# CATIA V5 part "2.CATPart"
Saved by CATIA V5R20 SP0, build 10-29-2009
Part number: 2
Publications: "H", "K", "Droite.1", "Droite.2", "Droite.3", "Plan.1"
Bounding box of the stored display mesh (mm): x -14 to 10, y 8.275 to 71.642, z -121.494 to -78.745
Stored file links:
  D:\Dropbox\IAO_2012\IAO_2012_815_gcordenod\IAO_2012_815_gcordenod\2.CATPart
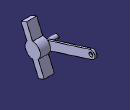
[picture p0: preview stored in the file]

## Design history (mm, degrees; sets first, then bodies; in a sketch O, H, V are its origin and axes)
Body1 (main body)
  Point1 "H": stored without definition
  Point2 "H": (0, 0, 0), relative to Point1
  Point3 "K": stored without definition
  Point4 "K": (0, 0, 0), relative to Point3
  Line1: type PtDir, RefPoint Point4, Direction yz-plane, Start -20, End 20
  Line2: type PtDir, RefPoint Point2, Direction yz-plane, Start -20, End 20
  Line3: type PtPt, FirstPoint Point2, SecondPoint Point4
  Plane1: type Offset, RefPlane yz-plane, Offset 0
  DatumCurve1
  Sketch1 on Plane1, origin (0, 0, 0), H (0, 1, 0), V (0, 0, 1)
    line L1 (21.241, -103.8788) -> (68.8628, -88.6419)
    arc A1 centre (67.6439, -84.8322) radius 4 from (68.8628, -88.6419) to (66.436, -81.0189) ccw
    point P3 (67.6439, -84.8322)
    line L2 (66.436, -81.0189) -> (18.7702, -96.1176)
    arc A2 centre (20, -100) radius 4.0725 from (18.7702, -96.1176) to (21.241, -103.8788) ccw
    point P6 (20, -100)
    reference projected point E1 (67.6439, -84.8322) from Point2
    reference projected point E2 (20, -100) from Point4
    circle A3 centre (67.6439, -84.8322) radius 2
    point P7 (67.6439, -84.8322)
    reference projected point E3 (67.6439, -84.8322) from Point2
    reference projected circle E4 centre (67.6439, -84.8322) radius 2 from edge of DatumCurve1
    radius A1 = 4
    tangency: A1 L1, L2 A1, A2 L1, A2 L2
    coincidence: E1 P3, E2 P6, E3 P7, A3 E4
  Pad1: profile Sketch1, direction (-1, 0, 0), length 2
  Point5 "K": stored without definition
  Point6 "K": stored without definition
  Sketch2 on start face of Pad1, origin (0, 0, 0), H (0, 1, 0), V (0, 0, 1)
    point P1 (20, -100)
    reference projected point E1 (20, -100) from Point4
    point P2 (14.3217, -95.1003)
    line L1 (14.3217, -95.1003) -> (8.2754, -81.1988)
    line L2 (8.2754, -81.1988) -> (13.9161, -78.7454)
    line L3 (13.9161, -78.7454) -> (19.8988, -92.5007)
    point P6 (25.4168, -105.1874)
    line L4 (25.4168, -105.1874) -> (31.4422, -119.0409)
    line L5 (31.4422, -119.0409) -> (25.8016, -121.4943)
    point P8 (25.8016, -121.4943)
    line L6 (25.8016, -121.4943) -> (19.7125, -107.4945)
    arc A1 centre (20, -100) radius 7.5 from (25.4168, -105.1874) to (19.8988, -92.5007) ccw
    point P10 (25.4168, -105.1874)
    arc A2 centre (20, -100) radius 7.5 from (14.3217, -95.1003) to (19.7125, -107.4945) ccw
    point P11 (14.3217, -95.1003)
    reference projected point E2 (20, -100) from Point5
    reference projected point E3 (20, -100) from Point6
    distance L4 E2 = 2.8983
    distance L6 E3 = 3.2528
    length L4 = 15.1072
    length L3 = 15
    coincidence: E1 P1, P6 L3, P8 L1, P10 L4, P11 L1, P6 P10, P2 P11
    perpendicularity: L2 L1
    parallelism: L3 L1, L4 L3, L5 L2, L6 L1
  Pad2: profile Sketch2, direction (1, 0, 0), length 10
  Sketch3 on end face of Pad1, origin (-2, 0, 0), H (0, -1, 0), V (0, 0, 1)
    circle A1 centre (-20, -100) radius 2
    point P1 (-20, -100)
    reference projected point E1 (-20, -100) from Point4
    radius A1 = 2
    coincidence: E1 P1
  Pad3: profile Sketch3, direction (-1, 0, 0), length 12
